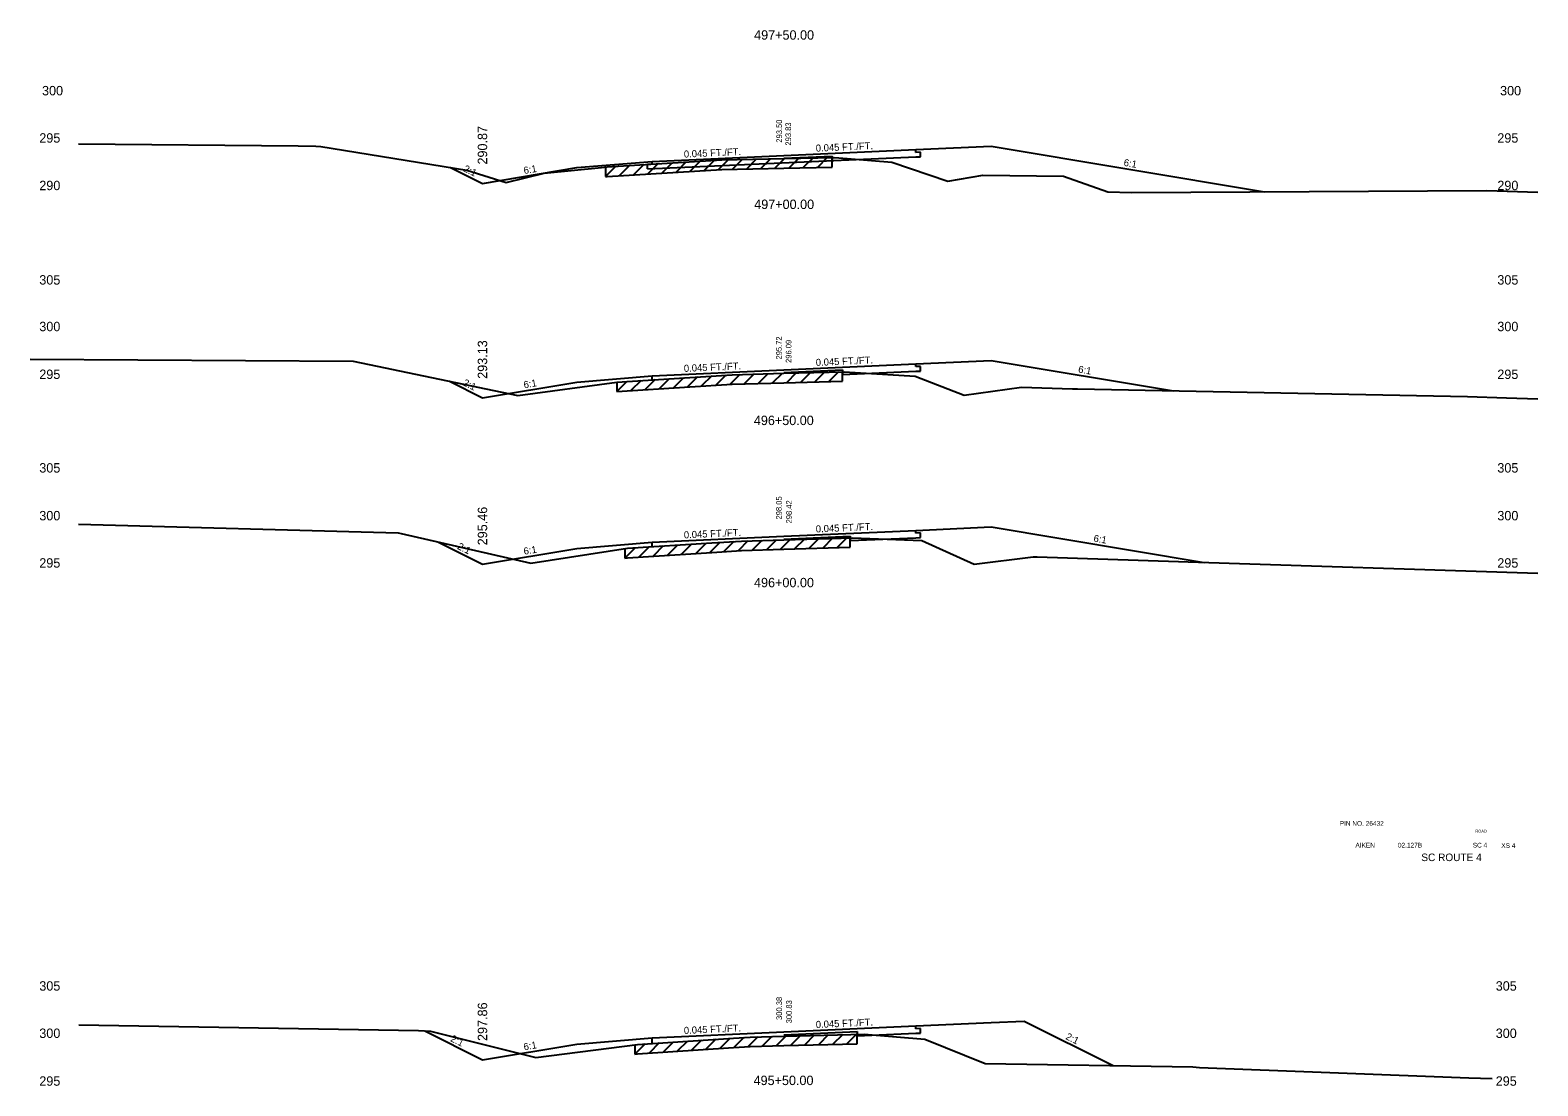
# Model space of a CAD drawing. Extents: x 883 to 1160, y 1002 to 4323.
# Drawn here: x 1000 to 1160, y 1420.1 to 1532.1 of the extents above; entities that cross this region are included whole.
import ezdxf

# ---------------------------------------------------------------- set-up
doc = ezdxf.new("R2010")
doc.units = 0
for name, color, linetype in [('Level 1', 7, 'Continuous'), ('Level 10', 7, 'Continuous'), ('Level 11', 7, 'Continuous'), ('Level 12', 7, 'Continuous'), ('Level 3', 7, 'Continuous'), ('Level 32', 7, 'Continuous'), ('Level 33', 7, 'Continuous'), ('Level 53', 7, 'Continuous'), ('Level 59', 7, 'Continuous'), ('Level 6', 7, 'Continuous'), ('Level 60', 7, 'Continuous'), ('Level 61', 7, 'Continuous'), ('Level 7', 7, 'Continuous')]:
    doc.layers.add(name, color=color, linetype=linetype)

msp = doc.modelspace()

# ---------------------------------------------------------------- linework, layer by layer
at = {"layer": 'Level 11'}
for p, q in [((1094, 1519.16), (1094, 1519.46)), ((1094.5, 1519.18), (1094, 1519.16)), ((1094, 1518.68), (1094.5, 1518.7)), ((1094.5, 1518.7), (1094.5, 1519.18)), ((1066, 1517.9), (1065.5, 1517.88)), ((1065.5, 1517.4), (1065.5, 1517.88)), ((1066, 1517.9), (1066, 1518.2)), ((1094, 1496.42), (1094, 1496.72)), ((1094.5, 1496.44), (1094, 1496.42)), ((1094.5, 1495.96), (1094.5, 1496.44)), ((1066, 1495.02), (1066, 1495.46)), ((1094, 1495.94), (1094.5, 1495.96)), ((1094, 1478.75), (1094, 1479.05)), ((1094.5, 1478.77), (1094, 1478.75)), ((1094.5, 1478.29), (1094.5, 1478.77)), ((1066, 1477.31), (1066, 1477.79)), ((1094, 1478.27), (1094.5, 1478.29)), ((1094, 1426.16), (1094, 1426.46)), ((1094.5, 1426.18), (1094, 1426.16)), ((1094, 1425.68), (1094.5, 1425.7)), ((1094.5, 1425.7), (1094.5, 1426.18)), ((1066, 1424.6), (1066, 1425.2))]:
    msp.add_line(p, q, dxfattribs=at)
at = {"layer": 'Level 12'}
for p, q in [((1065.5, 1517.4), (1094, 1518.68)), ((1085.11, 1518.6), (1085.11, 1518.28)), ((1086.22, 1495.59), (1094, 1495.94)), ((1086.22, 1495.87), (1086.22, 1495.59)), ((1087.03, 1477.96), (1094, 1478.27)), ((1087.03, 1478.26), (1087.03, 1477.96)), ((1087.76, 1425.4), (1094, 1425.68)), ((1087.76, 1425.57), (1087.76, 1425.4))]:
    msp.add_line(p, q, dxfattribs=at)
at = {"layer": 'Level 53'}
for p, q in [((1080, 1518.53), (1085.11, 1518.76)), ((1085.11, 1518.76), (1085.11, 1518.6)), ((1080, 1495.79), (1086.22, 1496.07)), ((1086.22, 1496.07), (1086.22, 1495.87)), ((1080, 1478.12), (1087.03, 1478.44)), ((1087.03, 1478.44), (1087.03, 1478.26)), ((1080, 1425.53), (1087.76, 1425.88)), ((1087.76, 1425.88), (1087.76, 1425.57))]:
    msp.add_line(p, q, dxfattribs=at)
at = {"layer": 'Level 59'}
for p, q in [((1066, 1518.2), (1080, 1518.83)), ((1080, 1518.83), (1094, 1519.46)), ((1066, 1495.46), (1080, 1496.09)), ((1080, 1496.09), (1094, 1496.72)), ((1066, 1477.79), (1080, 1478.42)), ((1080, 1478.42), (1094, 1479.05)), ((1066, 1425.2), (1080, 1425.83)), ((1080, 1425.83), (1094, 1426.46))]:
    msp.add_line(p, q, dxfattribs=at)
at = {"layer": 'Level 6'}
for p, q in [((1094, 1519.46), (1102, 1519.82)), ((1058, 1517.54), (1066, 1518.2)), ((1094, 1496.72), (1102, 1497.08)), ((1058, 1494.79), (1066, 1495.46)), ((1094, 1479.05), (1102, 1479.41)), ((1058, 1477.13), (1066, 1477.79)), ((1094, 1426.46), (1102, 1426.82)), ((1102, 1426.82), (1105.5, 1426.98)), ((1058, 1424.53), (1066, 1425.2))]:
    msp.add_line(p, q, dxfattribs=at)
at = {"layer": 'Level 60'}
for p, q in [((1005.12, 1520.05), (1028.45, 1519.85)), ((1028.45, 1519.85), (1030.31, 1519.82)), ((1030.31, 1519.82), (1030.85, 1519.79)), ((1030.85, 1519.79), (1046.34, 1517.28)), ((1073.41, 1518.36), (1080, 1518.5)), ((1080, 1518.5), (1085.41, 1518.61)), ((1085.41, 1518.61), (1091.43, 1518.13)), ((1046.34, 1517.28), (1050.5, 1515.97)), ((1050.5, 1515.97), (1054.55, 1516.97)), ((1054.55, 1516.97), (1060.63, 1517.56)), ((1060.63, 1517.56), (1061.22, 1517.61)), ((1061.22, 1517.61), (1073.41, 1518.36)), ((1091.43, 1518.13), (1097.38, 1516.09)), ((1097.38, 1516.09), (1101.11, 1516.75)), ((1101.11, 1516.75), (1109.65, 1516.65)), ((1109.65, 1516.65), (1114.37, 1514.97)), ((1114.37, 1514.97), (1116.86, 1514.92)), ((1116.86, 1514.92), (1154.57, 1515.11)), ((1154.57, 1515.11), (1160, 1514.95)), ((1000, 1497.23), (1034.29, 1497.02)), ((1034.29, 1497.02), (1051.75, 1493.36)), ((1051.75, 1493.36), (1062.25, 1494.78)), ((1062.25, 1494.78), (1070, 1495.28)), ((1070, 1495.28), (1074.49, 1495.57)), ((1074.49, 1495.57), (1080, 1495.72)), ((1080, 1495.72), (1086.39, 1495.87)), ((1086.39, 1495.87), (1093.91, 1495.4)), ((1093.91, 1495.4), (1099.11, 1493.41)), ((1099.11, 1493.41), (1105.19, 1494.24)), ((1105.19, 1494.24), (1110.63, 1494.07)), ((1110.63, 1494.07), (1111.14, 1494.06)), ((1111.14, 1494.06), (1152.53, 1493.25)), ((1152.53, 1493.25), (1156.68, 1493.11)), ((1156.68, 1493.11), (1160, 1493.01)), ((1005.13, 1479.69), (1039.04, 1478.77)), ((1039.04, 1478.77), (1039.37, 1478.7)), ((1039.37, 1478.7), (1053.14, 1475.56)), ((1053.14, 1475.56), (1063.39, 1477.15)), ((1063.39, 1477.15), (1072.35, 1477.71)), ((1072.35, 1477.71), (1075.49, 1477.91)), ((1075.49, 1477.91), (1080, 1478.05)), ((1080, 1478.05), (1087.26, 1478.27)), ((1087.26, 1478.27), (1094.63, 1477.97)), ((1094.63, 1477.97), (1100.19, 1475.46)), ((1100.19, 1475.46), (1106.45, 1476.24)), ((1106.45, 1476.24), (1106.88, 1476.24)), ((1106.88, 1476.24), (1121.86, 1475.74)), ((1121.86, 1475.74), (1122.89, 1475.7)), ((1122.89, 1475.7), (1160, 1474.51)), ((1005.15, 1426.56), (1041.2, 1425.97)), ((1041.2, 1425.97), (1042.47, 1425.89)), ((1042.47, 1425.89), (1053.66, 1423.09)), ((1053.66, 1423.09), (1064.45, 1424.5)), ((1064.45, 1424.5), (1074.63, 1425.17)), ((1074.63, 1425.17), (1076.41, 1425.28)), ((1076.41, 1425.28), (1080, 1425.38)), ((1080, 1425.38), (1088.51, 1425.59)), ((1088.51, 1425.59), (1094.95, 1425.07)), ((1094.95, 1425.07), (1101.35, 1422.46)), ((1101.35, 1422.46), (1123.38, 1422.13)), ((1123.38, 1422.13), (1124.1, 1422.06)), ((1124.1, 1422.06), (1152.66, 1420.95)), ((1152.66, 1420.95), (1155.16, 1420.89))]:
    msp.add_line(p, q, dxfattribs=at)
at = {"layer": 'Level 61'}
for p, q in [((1075.56, 1518.4), (1074.54, 1517.38)), ((1077.06, 1518.44), (1076.04, 1517.42)), ((1078.56, 1518.47), (1077.54, 1517.45)), ((1080.06, 1518.5), (1079.04, 1517.48)), ((1081.56, 1518.53), (1080.54, 1517.51)), ((1083.06, 1518.56), (1082.04, 1517.54)), ((1084.56, 1518.59), (1083.54, 1517.57)), ((1085.11, 1517.6), (1085.11, 1518.6)), ((1062.11, 1517.67), (1061.04, 1516.6)), ((1061.04, 1517.6), (1061.04, 1516.6)), ((1061.22, 1516.61), (1073.41, 1517.36)), ((1063.6, 1517.76), (1062.54, 1516.69)), ((1065.1, 1517.85), (1064.04, 1516.79)), ((1066.6, 1517.94), (1065.54, 1516.88)), ((1068.1, 1518.03), (1067.04, 1516.97)), ((1069.6, 1518.12), (1068.54, 1517.06)), ((1071.1, 1518.22), (1070.04, 1517.15)), ((1072.6, 1518.31), (1071.54, 1517.24)), ((1074.08, 1518.37), (1073.04, 1517.33)), ((1073.41, 1517.36), (1080, 1517.5)), ((1080, 1517.5), (1085.11, 1517.6)), ((1061.04, 1516.6), (1061.22, 1516.61)), ((1063.33, 1494.85), (1062.26, 1493.78)), ((1062.26, 1494.78), (1062.26, 1493.78)), ((1064.83, 1494.95), (1063.76, 1493.88)), ((1066.33, 1495.05), (1065.26, 1493.98)), ((1067.83, 1495.14), (1066.76, 1494.07)), ((1069.33, 1495.24), (1068.26, 1494.17)), ((1070.83, 1495.34), (1069.76, 1494.27)), ((1070, 1494.28), (1074.49, 1494.57)), ((1072.33, 1495.43), (1071.26, 1494.37)), ((1073.84, 1495.53), (1072.77, 1494.46)), ((1075.3, 1495.6), (1074.27, 1494.56)), ((1074.49, 1494.57), (1080, 1494.72)), ((1076.79, 1495.63), (1075.77, 1494.61)), ((1078.29, 1495.67), (1077.27, 1494.65)), ((1079.8, 1495.71), (1078.77, 1494.69)), ((1080, 1494.72), (1086.22, 1494.87)), ((1081.3, 1495.75), (1080.27, 1494.72)), ((1082.8, 1495.79), (1081.77, 1494.76)), ((1084.3, 1495.82), (1083.27, 1494.8)), ((1085.8, 1495.86), (1084.77, 1494.83)), ((1086.22, 1494.87), (1086.22, 1495.87)), ((1062.26, 1493.78), (1070, 1494.28)), ((1064.22, 1477.2), (1063.12, 1476.11)), ((1063.12, 1477.11), (1063.12, 1476.11)), ((1065.69, 1477.3), (1064.62, 1476.23)), ((1067.19, 1477.39), (1066.12, 1476.32)), ((1068.69, 1477.48), (1067.62, 1476.42)), ((1070.19, 1477.58), (1069.12, 1476.51)), ((1071.69, 1477.67), (1070.63, 1476.6)), ((1073.19, 1477.76), (1072.13, 1476.7)), ((1072.35, 1476.71), (1075.49, 1476.91)), ((1074.69, 1477.86), (1073.63, 1476.79)), ((1076.17, 1477.93), (1075.13, 1476.89)), ((1075.49, 1476.91), (1080, 1477.05)), ((1077.66, 1477.98), (1076.63, 1476.94)), ((1079.16, 1478.02), (1078.13, 1476.99)), ((1080.66, 1478.07), (1079.63, 1477.04)), ((1080, 1477.05), (1087.03, 1477.26)), ((1082.16, 1478.11), (1081.13, 1477.08)), ((1083.66, 1478.16), (1082.63, 1477.13)), ((1085.16, 1478.21), (1084.13, 1477.17)), ((1086.66, 1478.25), (1085.63, 1477.22)), ((1087.03, 1477.26), (1087.03, 1478.26)), ((1063.12, 1476.11), (1063.39, 1476.15)), ((1063.39, 1476.15), (1072.35, 1476.71)), ((1065.27, 1424.55), (1064.18, 1423.46)), ((1064.18, 1424.46), (1064.18, 1423.46)), ((1064.45, 1423.5), (1074.63, 1424.17)), ((1066.75, 1424.65), (1065.68, 1423.58)), ((1068.25, 1424.75), (1067.18, 1423.68)), ((1069.75, 1424.85), (1068.68, 1423.78)), ((1071.25, 1424.95), (1070.18, 1423.87)), ((1072.75, 1425.04), (1071.68, 1423.97)), ((1074.25, 1425.14), (1073.18, 1424.07)), ((1074.63, 1424.17), (1076.41, 1424.28)), ((1075.75, 1425.24), (1074.68, 1424.17)), ((1077.21, 1425.31), (1076.18, 1424.27)), ((1076.41, 1424.28), (1080, 1424.38)), ((1078.71, 1425.34), (1077.68, 1424.32)), ((1080.21, 1425.38), (1079.18, 1424.36)), ((1080, 1424.38), (1087.76, 1424.57)), ((1081.7, 1425.42), (1080.68, 1424.39)), ((1083.2, 1425.46), (1082.18, 1424.43)), ((1084.7, 1425.5), (1083.68, 1424.47)), ((1086.2, 1425.53), (1085.18, 1424.51)), ((1087.71, 1425.57), (1086.68, 1424.54)), ((1087.76, 1424.57), (1087.76, 1425.57)), ((1064.18, 1423.46), (1064.45, 1423.5))]:
    msp.add_line(p, q, dxfattribs=at)
at = {"layer": 'Level 7'}
for p, q in [((1102, 1519.82), (1130.99, 1514.99)), ((1044.62, 1517.56), (1048, 1515.87)), ((1048, 1515.87), (1058, 1517.54)), ((1102, 1497.08), (1121.33, 1493.86)), ((1044.49, 1494.88), (1048, 1493.13)), ((1048, 1493.13), (1058, 1494.79)), ((1102, 1479.41), (1124.58, 1475.65)), ((1043.32, 1477.8), (1048, 1475.46)), ((1048, 1475.46), (1058, 1477.13)), ((1041.87, 1425.93), (1048, 1422.86)), ((1105.5, 1426.98), (1114.94, 1422.26)), ((1048, 1422.86), (1058, 1424.53))]:
    msp.add_line(p, q, dxfattribs=at)

# ---------------------------------------------------------------- texts
at = {"layer": 'Level 1'}
for s, height, p in [('497+50.00', 1, (1076.83, 1531.12)), ('497+00.00', 1, (1076.84, 1513.15)), ('496+50.00', 1, (1076.8, 1490.22)), ('496+00.00', 1, (1076.82, 1473.01)), ('PIN NO. 26432', 0.5, (1138.97, 1447.7)), ('AIKEN', 0.5, (1140.64, 1445.39)), ('02.127B', 0.5, (1145.15, 1445.39)), ('SC 4', 0.5, (1153.09, 1445.39)), ('XS 4', 0.5, (1156.12, 1445.35)), ('SC ROUTE 4', 0.8, (1147.63, 1443.95)), ('495+50.00', 1, (1076.77, 1420.18))]:
    msp.add_text(s, height=height, dxfattribs=at).set_placement(p)
at = {"layer": 'Level 10'}
for s, p in [('293.50', (1079.79, 1520.19)), ('295.72', (1079.76, 1497.18)), ('298.05', (1079.76, 1480.2)), ('300.38', (1079.79, 1427.09))]:
    msp.add_text(s, height=0.6, rotation=90, dxfattribs=at).set_placement(p)
at = {"layer": 'Level 3'}
for s, height, p in [(' 300', 1, (1000.89, 1525.21)), (' 300', 1, (1155.62, 1525.21)), (' 295', 1, (1000.6, 1520.19)), (' 295', 1, (1155.33, 1520.19)), (' 290', 1, (1000.6, 1515.15)), (' 290', 1, (1155.33, 1515.15)), (' 305', 1, (1000.6, 1505.13)), (' 305', 1, (1155.33, 1505.13)), (' 300', 1, (1000.6, 1500.18)), (' 300', 1, (1155.33, 1500.18)), (' 295', 1, (1000.6, 1495.11)), (' 295', 1, (1155.33, 1495.11)), (' 305', 1, (1000.6, 1485.18)), (' 305', 1, (1155.33, 1485.18)), (' 300', 1, (1000.6, 1480.11)), (' 300', 1, (1155.33, 1480.11)), (' 295', 1, (1000.6, 1475.09)), (' 295', 1, (1155.33, 1475.09)), ('ROAD', 0.3, (1153.38, 1446.98)), (' 305', 1, (1000.6, 1430.2)), (' 305', 1, (1155.16, 1430.2)), (' 300', 1, (1000.6, 1425.18)), (' 300', 1, (1155.16, 1425.18)), (' 295', 1, (1000.6, 1420.11)), (' 295', 1, (1155.16, 1420.11))]:
    msp.add_text(s, height=height, dxfattribs=at).set_placement(p)
at = {"layer": 'Level 32'}
for s, rotation, p in [('0.045 FT./FT.', 2.5766, (1083.39, 1519.23)), ('0.045 FT./FT.', 2.5766, (1069.39, 1518.6)), ('6:1', 350.5377, (1116.01, 1517.74)), ('2:1', 333.435, (1045.91, 1517.19)), ('6:1', 9.4623, (1052.43, 1516.86)), ('0.045 FT./FT.', 2.5766, (1069.39, 1495.86)), ('0.045 FT./FT.', 2.5766, (1083.39, 1496.49)), ('6:1', 350.5377, (1111.18, 1495.8)), ('2:1', 333.435, (1045.85, 1494.48)), ('6:1', 9.4623, (1052.43, 1494.12)), ('0.045 FT./FT.', 2.5766, (1069.39, 1478.19)), ('0.045 FT./FT.', 2.5766, (1083.39, 1478.82)), ('6:1', 350.5377, (1112.81, 1477.86)), ('2:1', 333.435, (1045.27, 1477.11)), ('6:1', 9.4623, (1052.43, 1476.45)), ('0.045 FT./FT.', 2.5766, (1083.39, 1426.23)), ('0.045 FT./FT.', 2.5766, (1069.39, 1425.6)), ('2:1', 333.435, (1109.82, 1425.09)), ('2:1', 333.435, (1044.54, 1424.87)), ('6:1', 9.4623, (1052.43, 1423.86))]:
    msp.add_text(s, height=0.75, rotation=rotation, dxfattribs=at).set_placement(p)
at = {"layer": 'Level 33'}
for s, p in [('290.87', (1048.5, 1517.87)), ('293.13', (1048.5, 1495.13)), ('295.46', (1048.5, 1477.46)), ('297.86', (1048.5, 1424.86))]:
    msp.add_text(s, height=1, rotation=90, dxfattribs=at).set_placement(p)
at = {"layer": 'Level 59'}
for s, p in [(' 293.83', (1080.75, 1519.66)), (' 296.09', (1080.79, 1496.59)), (' 298.42', (1080.83, 1479.56)), (' 300.83', (1080.83, 1426.51))]:
    msp.add_text(s, height=0.6, rotation=90, dxfattribs=at).set_placement(p)

doc.saveas('drawing.dxf')
